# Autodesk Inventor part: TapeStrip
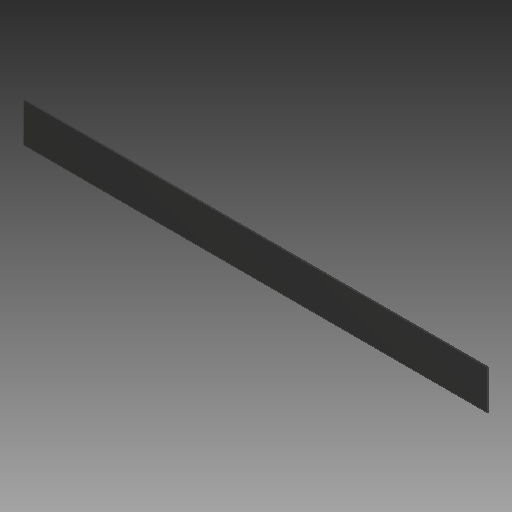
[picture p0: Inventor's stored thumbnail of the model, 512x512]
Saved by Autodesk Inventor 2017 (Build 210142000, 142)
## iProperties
Created: 2017-05
Part Number: TapeStrip
Material: Generic
Document SubType Name: Modeling
Designer: Savy
Density: 1 g/cm^3
Appearance: Default
Author: Savy
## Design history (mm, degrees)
feature "Base1"
body "Solid1"
